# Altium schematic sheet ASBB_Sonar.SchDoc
size A4
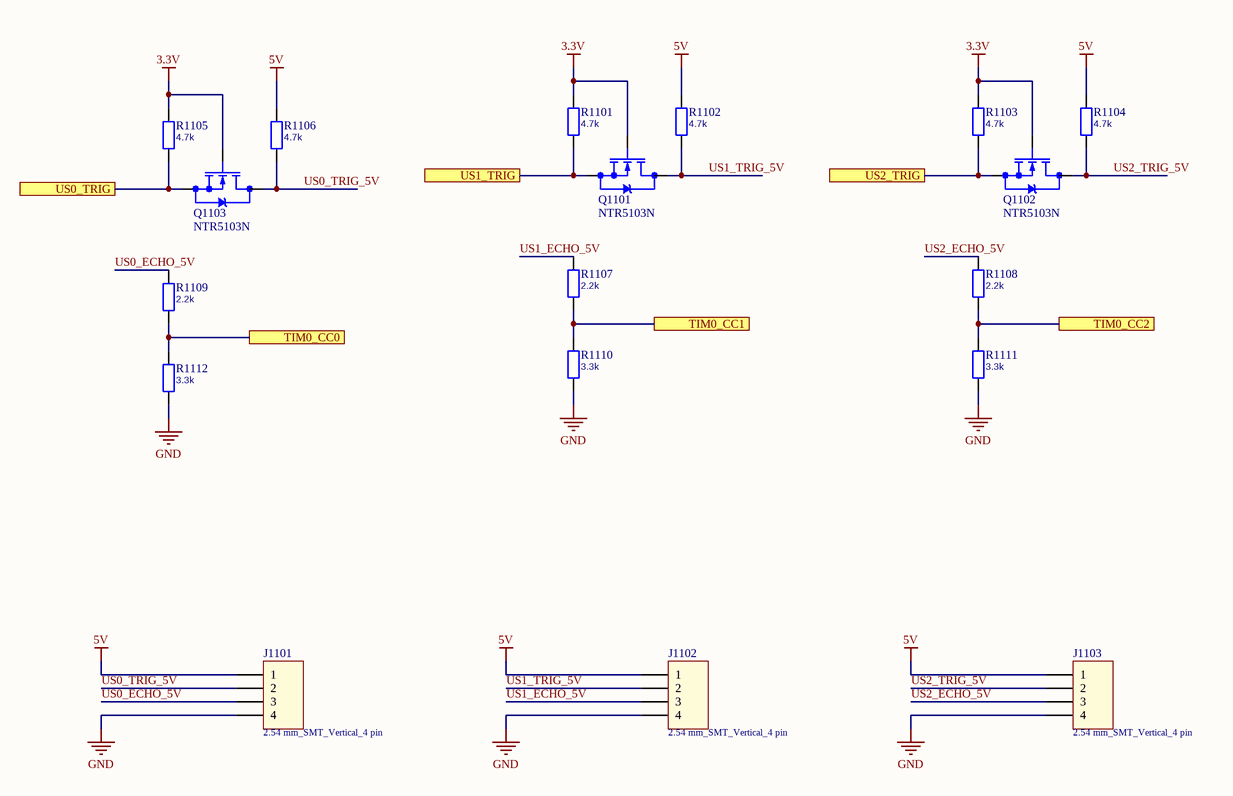
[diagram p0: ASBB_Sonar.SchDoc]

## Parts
J1101  2.54 mm_SMT_Vertical_4 pin  [61000411921]
J1102  2.54 mm_SMT_Vertical_4 pin  [61000411921]
J1103  2.54 mm_SMT_Vertical_4 pin  [61000411921]
Q1101  NTR5103N  [SOT23]
Q1102  NTR5103N  [SOT23]
Q1103  NTR5103N  [SOT23]
R1101  4.7k  [0603]
R1102  4.7k  [0603]
R1103  4.7k  [0603]
R1104  4.7k  [0603]
R1105  4.7k  [0603]
R1106  4.7k  [0603]
R1107  2.2k  [0603]
R1108  2.2k  [0603]
R1109  2.2k  [0603]
R1110  3.3k  [0603]
R1111  3.3k  [0603]
R1112  3.3k  [0603]

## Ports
TIM0_CC0, TIM0_CC1, TIM0_CC2, US0_TRIG, US1_TRIG, US2_TRIG

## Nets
3.3V: Q1101.1(G) Q1102.1(G) Q1103.1(G) R1101.2 R1103.2 R1105.2
5V: J1101.1 J1102.1 J1103.1 R1102.2 R1104.2 R1106.2
GND: J1101.4 J1102.4 J1103.4 R1110.1 R1111.1 R1112.1
TIM0_CC0: R1109.1 R1112.2 ; port TIM0_CC0
TIM0_CC1: R1107.1 R1110.2 ; port TIM0_CC1
TIM0_CC2: R1108.1 R1111.2 ; port TIM0_CC2
US0_ECHO_5V: J1101.3 R1109.2
US0_TRIG: Q1103.2(S) R1105.1 ; port US0_TRIG
US0_TRIG_5V: J1101.2 Q1103.3(D) R1106.1
US1_ECHO_5V: J1102.3 R1107.2
US1_TRIG: Q1101.2(S) R1101.1 ; port US1_TRIG
US1_TRIG_5V: J1102.2 Q1101.3(D) R1102.1
US2_ECHO_5V: J1103.3 R1108.2
US2_TRIG: Q1102.2(S) R1103.1 ; port US2_TRIG
US2_TRIG_5V: J1103.2 Q1102.3(D) R1104.1

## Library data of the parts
J1101-J1103 = 61000411921: Socket Header WR-PHD, Pitch 2.54 mm, SMT, Vertical, single row, 4 pin; Rated Current: 3 A; Pin Number: 4; Pitch: 2.54 mm; Working Voltage: 250 VAC; Contact Resistance: 20 mOhm; Insulation Resistance: >1000 MOhm
Q1101-Q1103 = NMOS SOT23: N-Channel MOSFET SOT23
R1101-R1112 = Resistor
